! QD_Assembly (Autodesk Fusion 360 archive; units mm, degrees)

design "! QD_Assembly" references "Inlet Probe", "3/16  Stainless Steel Ball 9291K45", "PC085-1225-3380-SST-0880-CG-N-IN", "Sleeve", "Outlet Port", "Modeled Plateless Cylinder Housing", "PC085-1225-3380-SST-0880-CG-N-IN", "No. 19 1/16  PTFE O-ring 9559k114", "1.25  Bore, 1.5  Stroke Pneumatic Cylinder 4952K718", "Retainer", "3/4  Self Lock Snap Ring 98368A190"
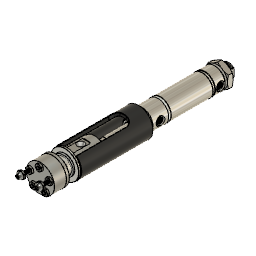
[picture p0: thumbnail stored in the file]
description: Part Number
part number: 92210A324_18-8 Stainless Steel Hex Drive Flat Head Screw
part number: 91841A195_Corrosion-Resistant 18-8 Stainless Steel Hex Nuts
part number: 92210A312_18-8 Stainless Steel Hex Drive Flat Head Screw
part number: 94301A125_Open-End Cap Nut
component_insert "Component Insert1"
component_insert "Component Insert2"
joint "Assemble" alignAngle 0 alignOffsetX 0 alignOffsetY 0 alignOffsetZ 0
component_insert "Component Insert3"
joint "Assemble" alignAngle 0 alignOffsetX 0 alignOffsetY 0 alignOffsetZ 0
joint "Assemble" alignAngle 0 alignOffsetX 0 alignOffsetY 0 alignOffsetZ 0
component_insert "Component Insert4"
joint "Assemble" alignAngle 0 alignOffsetX 0 alignOffsetY 0 alignOffsetZ 0
component_insert "Component Insert5"
joint "Assemble" alignAngle 0 alignOffsetX 0 alignOffsetY 0 alignOffsetZ 0
component_insert "Component Insert6"
step "GeometricRelationship1" Offset 0
joint "Assemble" alignAngle 0 alignOffsetX 0 alignOffsetY 0 alignOffsetZ 0
position "Position1"
component_insert "Component Insert8"
joint "Assemble" alignAngle 180 alignOffsetX 0 alignOffsetY 0 alignOffsetZ 0
component_insert "Component Insert9"
step "GeometricRelationship3" Offset 0
position "Position2"
joint "Assemble" alignAngle 0 alignOffsetX 0 alignOffsetY 0 alignOffsetZ 0
component_insert "Component Insert12"
joint "Assemble" alignAngle 0 alignOffsetX 0 alignOffsetY 0 alignOffsetZ 0
step "GeometricRelationship4" Offset 0
base_feature "Base Feature1"
step "GeometricRelationship5" Offset 0
base_feature "Base Feature1"
step "GeometricRelationship6" Offset 0
position "Position3"
circular_pattern "C-Pattern1" TotalAngle 360
circular_pattern "C-Pattern1" TotalAngle 360
component_insert "Component Insert13"
component_insert "Component Insert14"
base_feature "Base Feature1"
step "GeometricRelationship7" Offset 0
base_feature "Base Feature1"
step "GeometricRelationship8" Offset 10.16
position "Position4"
mirror "Mirror1" mirrorStitchTolerance 0.1001
mirror "Mirror1" mirrorStitchTolerance 0.1001
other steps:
create_component "CreateComponent1"
create_component "CreateComponent2"
create_component "CreateComponent3"
create_component "CreateComponent4"

design "PC085-1225-3380-SST-0880-CG-N-IN"
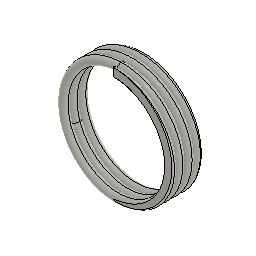
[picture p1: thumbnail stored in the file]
description: Part Number
part number: ANIMATE_PC
base_feature "Base Feature"

design "Retainer"
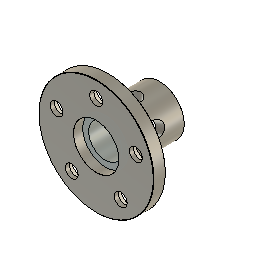
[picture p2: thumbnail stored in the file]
sketch "Sketch1" plane through (0, 0, 0) normal (1, 0, 0) x axis (0, 1, 0)
  line L1 (0, 8.7376) -> (0, 22.225)
  line L2 (3.556, 8.7376) -> (0, 8.7376)
  line L3 (3.556, 6.4389) -> (3.556, 8.7376)
  line L4 (24.638, 6.4389) -> (3.556, 6.4389)
  line L5 (24.638, 9.525) -> (24.638, 6.4389)
  line L6 (4.7625, 9.525) -> (24.638, 9.525)
  line L7 (4.7625, 22.225) -> (4.7625, 9.525)
  line L8 (0, 22.225) -> (4.7625, 22.225)
  line L9 (24.13, 9.144) -> (24.13, 9.525)
  line L10 (22.13, 9.144) -> (24.13, 9.144)
  line L11 (22.13, 9.525) -> (22.13, 9.144)
  point P1 (0, 0)
  point P3 (0, 8.7376)
  point P10 (24.13, 9.525)
  point P13 (22.13, 9.525)
  point P2 (0, 22.225)
  point P9 (4.7625, 22.225)
  point P4 (3.556, 8.7376)
  point P7 (24.638, 9.525)
  point P11 (24.13, 9.144)
  point P12 (22.13, 9.144)
  vertical L1
  perpendicular L1 L2
  perpendicular L2 L3
  perpendicular L3 L4
  perpendicular L4 L5
  perpendicular L5 L6
  perpendicular L6 L7
  perpendicular L1 L8
  vertical P1 P3
  coincident L6 P10
  perpendicular L6 L9
  perpendicular L5 L10
  coincident L6 P13
  perpendicular L6 L11
  dimension "d1" distance P2 P9 = 4.7625
  dimension "d2" distance P1 L4 = 6.4389 (= "( ( 0.5 + 0.006 + 0.001 ) / 2 ) * 1 in")
  dimension "d3" distance P1 L2 = 8.7376 (= "( ( 0.5 + 0.187 + 0.001 ) / 2 ) * 1 in")
  dimension "d4" distance P3 P4 = 3.556
  dimension "d5" distance P1 L8 = 22.225 (= "( 1.75 / 2 ) * 1 in")
  dimension "d6" distance P2 P7 = 24.638
  dimension "d7" distance P1 L6 = 9.525
  dimension "d45" distance P11 P12 = 2
  dimension "d46" distance P1 L10 = 9.144 (= "( 0.72 / 2 ) * 1 in")
  dimension "d47" distance L5 L9 = 0.508
revolve "Revolve1" sketch "Sketch1" AlongAngle 360
sketch "Sketch2" plane through (0, 0, 0) normal (1, 0, 0) x axis (0, 1, 0)
  line L1 (12.0759, 6.4389) -> (11.5318, 9.525)
  line L2 (4.7625, 9.525) -> (24.638, 9.525)
  line L3 (24.638, 6.4389) -> (3.556, 6.4389)
  line L4 (14.4189, 6.4389) -> (14.4189, 9.525)
  line L5 (12.2478, 5.4642) -> (11.5318, 9.525)
  line L6 (14.4189, 5.4642) -> (12.2478, 5.4642)
  line L7 (14.4189, 6.4389) -> (14.4189, 5.4642)
  line L8 (14.4189, 9.525) -> (17.306, 9.525)
  line L9 (16.59, 5.4642) -> (17.306, 9.525)
  line L10 (14.4189, 5.4642) -> (16.59, 5.4642)
  circle C1 centre (14.4189, 6.8644) radius 2.3813
  point P2 (11.5318, 9.525)
  point P3 (12.0759, 6.4389)
  point P8 (14.4189, 9.525)
  point P9 (14.4189, 6.4389)
  point P12 (17.306, 9.525)
  point P13 (14.4189, 9.525)
  point P10 (12.2478, 5.4642)
  point P14 (16.59, 5.4642)
  point P11 (14.4189, 5.4642)
  point P15 (14.4189, 5.4642)
  point P16 (14.4189, 6.8644)
  coincident P2 L2
  coincident P3 L3
  coincident L2 P8
  coincident L3 P9
  vertical L4
  parallel L1 L5
  perpendicular L4 L6
  perpendicular L3 L7
  symmetric P2 L4 P12
  symmetric P8 L4 P13
  symmetric L4 P10 P14
  symmetric L4 P11 P15
  coincident L4 P16
  tangent L5 C1
  dimension "d27" angle L1 L2 = 80
  dimension "d33" diameter C1 = 4.7625 (= "( 3 / 16 ) * 1 in")
  dimension "d44" distance P13 P16 = 2.6606 (= "( 0.1875 / 2 ) * 1 in + 0.011 in")
revolve "Revolve2" sketch "Sketch2" AlongAngle 360
circular_pattern "C-Pattern1" TotalAngle 360
sketch "Sketch4" plane through (0, 4.7625, 0) normal (0, 1, 0) x axis (-1, 0, 0)
  circle C1 centre (0, 16.129) radius 2.4892
  circle C2 centre (0, 0) radius 22.225
  circle C3 centre (0, 0) radius 9.525
  point P2 (0, 0)
  point P3 (0, 16.129)
  vertical P2 P3
  dimension "d18" diameter C1 = 4.9784
  dimension "d19" distance P2 P3 = 16.129
hole "Hole1" HoleDepth 5.08 HoleDiameter 4.9784 TipAngle 118 CSDiameter 10.4394 CSAngle 82
circular_pattern "C-Pattern2" TotalAngle 360
fillet "Fillet2" radius 0.127
fillet "Fillet3" radius 0.254
chamfer "Chamfer4" distance 0.127
chamfer "Chamfer5" distance 0.0254
fillet "Fillet4" radius 1.016
sketch "Sketch5" plane through (0, 3.556, 0) normal (0, -1, 0) x axis (1, 0, 0)
  circle C1 centre (0, 0) radius 6.4389
  circle C2 centre (0, 0) radius 8.7376

design "Outlet Port"
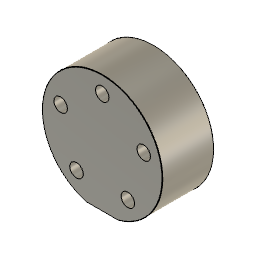
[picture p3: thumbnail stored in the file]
sketch "Sketch1" plane through (0, 0, 0) normal (1, 0, 0) x axis (0, 1, 0)
  line L1 (109.277, 0) -> (0, 0)
  line L2 (0, 6.604) -> (0, 22.225)
  line L3 (19.05, 6.604) -> (0, 6.604)
  line L4 (0, 22.225) -> (19.05, 22.225)
  line L5 (19.05, 11.9507) -> (19.05, 22.225)
  line L6 (17.6784, 11.9507) -> (19.05, 11.9507)
  line L7 (17.6784, 9.3345) -> (17.6784, 11.9507)
  line L8 (19.05, 9.3345) -> (17.6784, 9.3345)
  line L9 (19.05, 6.604) -> (19.05, 9.3345)
  line L10 (0, 0) -> (0, 6.604)
  line L11 (19.05, 0) -> (19.05, 6.604)
  line L12 (19.05, 0) -> (0, 0)
  point P1 (0, 0)
  point P2 (0, 0)
  point P5 (0, 6.604)
  point P8 (19.05, 11.9507)
  point P11 (19.05, 9.3345)
  point P12 (0, 0)
  point P13 (19.05, 0)
  point P14 (0, 0)
  point P4 (0, 22.225)
  point P7 (19.05, 22.225)
  point P9 (17.6784, 11.9507)
  coincident P1 P2
  horizontal L1
  vertical L2
  perpendicular L2 L3
  perpendicular L2 L4
  perpendicular L4 L5
  perpendicular L5 L6
  perpendicular L6 L7
  perpendicular L7 L8
  perpendicular L3 L9
  vertical P1 P5
  vertical P8 P11
  coincident P1 P12
  coincident L1 P13
  perpendicular L1 L11
  coincident P1 P14
  dimension "d1" distance P4 P7 = 19.05
  dimension "d2" distance P1 L4 = 22.225 (= "( 1.75 / 2 ) * 1 in")
  dimension "d3" distance P1 L3 = 6.604 (= "0.25 in + 0.01 in")
  dimension "d4" distance L1 L6 = 11.9507
  dimension "d5" distance L1 L8 = 9.3345
  dimension "d6" distance P8 P9 = 1.3716
revolve "Revolve1" sketch "Sketch1" AlongAngle 360
sketch "Sketch2" plane through (0, 0, 0) normal (0, -1, 0) x axis (1, 0, 0)
  circle C1 centre (0, 16.129) radius 2.4892
  circle C2 centre (0, 0) radius 22.225
  point P1 (0, 0)
  point P2 (0, 16.129)
  vertical P1 P2
  dimension "d10" diameter C1 = 4.9784
  dimension "d24" distance P1 P2 = 16.129
extrude "Extrude1" cut sketch "Sketch2" profile of C1 to an object
circular_pattern "C-Pattern1" TotalAngle 360
work_plane "WorkPlane1" RotateAngle 90
sketch "Sketch3" plane through (0, 0, 0) normal (0, -1, 0) x axis (1, 0, 0)
  circle C1 centre (-15.3396, 4.9841) radius 2.4892
  circle C2 centre (-9.4804, -13.0486) radius 2.4892
  circle C3 centre (9.4804, -13.0486) radius 2.4892
  circle C4 centre (15.3396, 4.9841) radius 2.4892
  circle C5 centre (0, 16.129) radius 2.4892
  circle C6 centre (0, 0) radius 22.225
hole "Hole2" HoleDepth 15.621 HoleDiameter 13.716 TipAngle 180
chamfer "Chamfer3" distance 0.127
chamfer "Chamfer4" distance 0.127
sketch "Sketch7" plane through (0, 0, -22.225) normal (0, 0, -1) x axis (-1, 0, 0)
  line L1 (6.985, 15.875) -> (-6.985, 15.875)
  line L2 (6.985, 1.905) -> (6.985, 15.875)
  line L3 (-6.985, 1.905) -> (6.985, 1.905)
  line L4 (-6.985, 15.875) -> (-6.985, 1.905)
  line L5 (0, 4.9156) -> (0, 1.905)
  line L6 (-1.263, 8.89) -> (6.985, 8.89)
  line L7 (0, 19.05) -> (0, 0)
  point P6 (0, 1.905)
  point P8 (6.985, 8.89)
  point P1 (0, 0)
  point P10 (0, 0)
  point P7 (0, 4.9156)
  point P2 (-6.985, 15.875)
  point P3 (6.985, 15.875)
  horizontal L1
  vertical L2
  horizontal L3
  vertical L4
  equal L1 L2
  midpoint L3 P6
  perpendicular L3 L5
  midpoint L2 P8
  perpendicular L2 L6
  coincident P1 P10
  vertical L7
  coincident P7 L7
  dimension "d33" distance P2 P3 = 13.97
  dimension "d34" distance P1 L6 = 8.89
extrude "Extrude2" add sketch "Sketch7" profile of L1 L2 L3 L4 against normal blind 2.54
sketch "Sketch8" plane through (0, 0, -22.225) normal (0, 0, -1) x axis (1, 0, 0)
  line L1 (6.985, -15.875) -> (0, -15.875)
  line L2 (6.985, -1.905) -> (6.985, -15.875)
  line L3 (0, -1.905) -> (6.985, -1.905)
  line L4 (-6.985, -1.905) -> (0, -1.905)
  line L5 (-6.985, -15.875) -> (-6.985, -1.905)
  line L6 (0, -15.875) -> (-6.985, -15.875)
  line L7 (0, -19.05) -> (0, 0)
  line L8 (-22.098, -19.05) -> (22.098, -19.05)
  line L9 (22.098, 0) -> (-22.098, 0)
  line L10 (22.098, 0) -> (-22.098, 0)
  line L11 (22.098, -19.05) -> (22.098, 0)
  line L12 (-22.098, -19.05) -> (22.098, -19.05)
  line L13 (-22.098, 0) -> (-22.098, -19.05)
  circle C1 centre (0, -8.89) radius 1.27
  point P1 (0, 0)
  point P9 (0, 0)
  point P10 (0, -19.05)
  point P8 (0, -8.89)
  point P11 (22.098, -19.05)
  point P17 (22.098, -19.05)
  point P13 (-22.098, 0)
  point P15 (-22.098, 0)
  coincident P1 P9
  perpendicular L6 L7
  coincident P10 L8
  coincident P8 L7
  horizontal L10
  vertical L11
  horizontal L12
  vertical L13
  coincident P11 P17
  coincident P13 P15
  dimension "d37" diameter C1 = 2.54
  dimension "d43" distance P8 L9 = 8.89
hole "Hole3" HoleDepth 20.32 HoleDiameter 10.7188 TipAngle 118
extrude "Extrude3" cut sketch "Sketch8" profile of L1 L2 L3 L4 L5 L6 C1 L10 L11 L12 L13 against normal blind 0.889
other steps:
thread "Thread2" ThreadOffset 0 ThreadDepth 0

design "1.25  Bore, 1.5  Stroke Pneumatic Cylinder 4952K718"
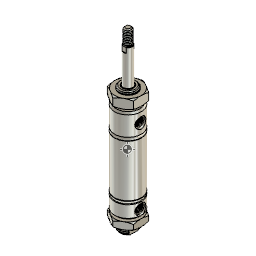
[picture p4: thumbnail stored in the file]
description: Part Number
part number: 4952K718_Round Body Air Cylinder
base_feature "Base Feature"
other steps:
create_component "CreateComponent1"

design "3/16  Stainless Steel Ball 9291K45"
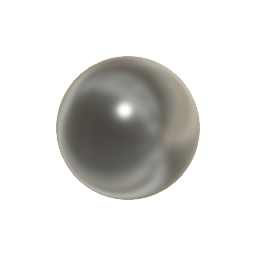
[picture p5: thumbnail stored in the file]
description: Part Number
part number: 9291K45_Tight-Tolerance Multipurpose 304 Stainless Steel Ball
base_feature "Base Feature"
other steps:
create_component "CreateComponent1"

design "No. 19 1/16  PTFE O-ring 9559k114"
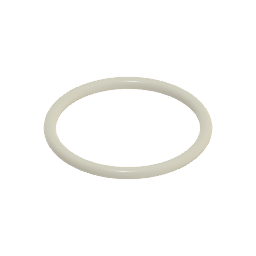
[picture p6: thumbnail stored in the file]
description: Part Number
part number: 9559K114_Ultra-Chemical-Resistant Rigid PTFE O-Ring
base_feature "Base Feature"
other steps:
create_component "CreateComponent1"

design "Modeled Plateless Cylinder Housing"
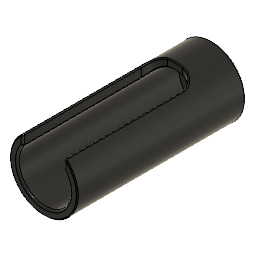
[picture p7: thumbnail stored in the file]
parameter "d85" = 360
parameter "d95" = 360
sketch "Sketch1" plane through (0, 0, 0) normal (1, 0, 0) x axis (0, 1, 0)
  line L1 (104.14, 17.78) -> (0, 17.78)
  line L2 (0, 17.78) -> (0, 22.86)
  line L3 (114.3, 22.86) -> (0, 22.86)
  line L4 (0, 0) -> (114.3, 0)
  line L5 (114.3, 17.78) -> (104.14, 17.78)
  line L6 (114.3, 22.86) -> (114.3, 17.78)
  line L7 (114.3, 8.7313) -> (114.3, 17.78)
  line L8 (109.22, 8.7313) -> (114.3, 8.7313)
  line L9 (109.22, 17.78) -> (109.22, 8.7313)
  point P5 (114.3, 0)
  point P6 (114.3, 22.86)
  point P3 (0, 17.78)
  point P4 (104.14, 17.78)
  point P2 (0, 22.86)
  point P1 (0, 0)
  point P7 (0, 0)
  point P11 (109.22, 17.78)
  point P9 (114.3, 8.7313)
  point P10 (109.22, 8.7313)
  vertical P5 P6
  horizontal P3 P4
  vertical P2 P3
  vertical P1 P3
  horizontal P2 P6
  coincident P1 P7
  parallel L1 L5
  perpendicular L3 L6
  perpendicular L5 L7
  perpendicular L6 L8
  coincident L5 P11
  perpendicular L5 L9
  dimension "d1" distance P2 P6 = 114.3
  dimension "d3" distance P1 L1 = 17.78
  dimension "d14" distance L1 L3 = 5.08
  dimension "d110" = 17.4625
  dimension "d113" distance P9 P10 = 5.08
  dimension "d82" Offset = 0
  dimension "d83" Angle = 0
  dimension "d91" Offset = 0
  dimension "d92" Offset = 0
  dimension "d93" Offset = 0
  dimension "d98" AlongDistance = -6.35
  dimension "d99" TaperAngle = 0
  dimension "d101" Radius = 15.24
  dimension "d103" Radius = 0.635
  dimension "d105" Radius = 0.635
revolve "Revolve1" sketch "Sketch1" AlongAngle 360
sketch "Sketch3" plane through (0, 0, 0) normal (0, 0, 1) x axis (1, 0, 0)
  line L1 (13.97, 0) -> (-13.97, 0)
  line L2 (13.97, 88.9) -> (13.97, 0)
  line L3 (-13.97, 88.9) -> (13.97, 88.9)
  line L4 (-13.97, 0) -> (-13.97, 88.9)
  point P1 (0, 0)
  point P2 (-13.97, 0)
  point P3 (13.97, 0)
  point P5 (-13.97, 88.9)
  horizontal L1
  vertical L2
  horizontal L3
  vertical L4
  coincident P1 L1
  midpoint P1 L1
  dimension "d7" distance P2 P3 = 27.94
  dimension "d8" distance P2 P5 = 88.9
extrude "Extrude1" cut sketch "Sketch3" along normal blind 30.48
chamfer "Chamfer2" distance 0.508
fillet "Fillet1" radius 8.89
sketch "Sketch4" plane through (0, 114.3, 0) normal (0, 1, 0) x axis (-1, 0, 0)
  line L1 (5.5825, -29.1664) -> (2.8706, -33.9505)
  line L2 (2.7953, -24.4258) -> (5.5825, -29.1664)
  line L3 (-2.7038, -24.4693) -> (2.7953, -24.4258)
  line L4 (-5.4157, -29.2534) -> (-2.7038, -24.4693)
  line L5 (-2.6284, -33.994) -> (-5.4157, -29.2534)
  line L6 (2.8706, -33.9505) -> (-2.6284, -33.994)
  line L7 (28.042, 9.9366) -> (22.5429, 9.8931)
  line L8 (30.7539, 14.7207) -> (28.042, 9.9366)
  line L9 (27.9667, 19.4613) -> (30.7539, 14.7207)
  line L10 (22.4676, 19.4178) -> (27.9667, 19.4613)
  line L11 (19.7557, 14.6337) -> (22.4676, 19.4178)
  line L12 (22.5429, 9.8931) -> (19.7557, 14.6337)
  line L13 (-22.6263, 19.3168) -> (-19.8391, 14.5762)
  line L14 (-28.1254, 19.2733) -> (-22.6263, 19.3168)
  line L15 (-30.8373, 14.4892) -> (-28.1254, 19.2733)
  line L16 (-28.0501, 9.7486) -> (-30.8373, 14.4892)
  line L17 (-22.551, 9.7921) -> (-28.0501, 9.7486)
  line L18 (-19.8391, 14.5762) -> (-22.551, 9.7921)
  line L19 (-5.4715, -22.1955) -> (-5.4157, -29.2534)
  line L20 (5.5272, -22.1817) -> (5.5825, -29.1664)
  line L21 (21.9577, 6.3593) -> (28.042, 9.9366)
  line L22 (16.4463, 15.8776) -> (22.4676, 19.4178)
  line L23 (-16.4862, 15.8362) -> (-22.6263, 19.3168)
  line L24 (-21.9736, 6.3041) -> (-28.0501, 9.7486)
  circle C1 centre (0, 0) radius 22.86
  circle C2 centre (0, 0) radius 12.7
  circle C3 centre (0.0834, -29.2099) radius 2.4765
  circle C4 centre (25.2548, 14.6772) radius 2.4765
  circle C5 centre (-25.3382, 14.5327) radius 2.4765
  circle C6 centre (0.0834, -29.2099) radius 5.4993
  circle C7 centre (25.2548, 14.6772) radius 5.4993
  circle C8 centre (-25.3382, 14.5327) radius 5.4993
  arc A1 centre (0, 0) radius 22.86 clockwise from (0, 0) to (0, 0)
  circle C9 centre (0, 0) radius 22.86
  circle C10 centre (0, 0) radius 8.7313
  point P1 (0, 0)
  point P3 (0, 0)
  point P4 (0.0834, -29.2099)
  point P13 (0.0834, -29.2099)
  point P7 (2.8706, -33.9505)
  point P30 (0, 0)
  point P31 (-5.4715, -22.1955)
  point P32 (5.5272, -22.1817)
  coincident P1 P3
  coincident P4 P13
  concentric C3 C6
  coincident P7 C6
  coincident P3 P30
  coincident C1 P31
  tangent C6 L19
  coincident A1 P32
  tangent C6 L20
  parallel L19 L20
  dimension "d17" diameter C3 = 4.953
  dimension "d18" distance P3 P4 = 29.21
  dimension "d24" distance L3 L6 = 9.525
  dimension "d20" C-Pattern1-Angle = 360
  dimension "d26" C-Pattern2-Angle = 360
  dimension "d97" C-Pattern3-Angle = 360
fillet "Fillet20" radius 1.27
fillet "Fillet23" radius 0.635 0.635
fillet "Fillet24" radius 1.27

design "Sleeve"
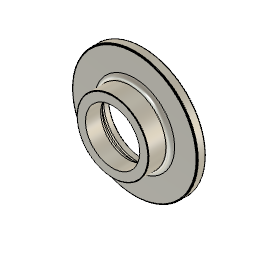
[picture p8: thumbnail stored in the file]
sketch "Sketch1" plane through (0, 0, 0) normal (1, 0, 0) x axis (0, 1, 0)
  line L1 (0, 9.6012) -> (0, 12.7)
  line L2 (5.9182, 9.6012) -> (0, 9.6012)
  line L3 (8.382, 12.065) -> (5.9182, 9.6012)
  line L4 (10.922, 12.065) -> (8.382, 12.065)
  line L5 (10.922, 22.225) -> (10.922, 12.065)
  line L6 (7.747, 22.225) -> (10.922, 22.225)
  line L7 (7.747, 12.7) -> (7.747, 22.225)
  line L8 (0, 12.7) -> (7.747, 12.7)
  line L9 (25.8911, 9.6012) -> (5.9182, 9.6012)
  point P1 (0, 0)
  point P2 (0, 9.6012)
  point P4 (8.382, 12.065)
  point P5 (10.922, 12.065)
  point P6 (10.922, 22.225)
  point P7 (7.747, 22.225)
  point P8 (7.747, 12.7)
  point P9 (0, 12.7)
  vertical L1
  perpendicular L1 L2
  perpendicular L1 L4
  perpendicular L4 L5
  perpendicular L5 L6
  perpendicular L6 L7
  perpendicular L1 L8
  vertical P1 P2
  parallel L2 L9
  dimension "d1" distance P1 L2 = 9.6012 (= "0.375 in + 0.003 in")
  dimension "d2" distance P1 L8 = 12.7
  dimension "d4" angle L3 L9 = 45
  dimension "d5" distance P4 P5 = 2.54
  dimension "d6" distance P6 P7 = 3.175
  dimension "d7" distance P1 L6 = 22.225
  dimension "d8" distance P8 P9 = 7.747
  dimension "d9" distance P1 L4 = 12.065
revolve "Revolve1" sketch "Sketch1" AlongAngle 360
fillet "Fillet1" radius 1.27
fillet "Fillet2" radius 1.524
chamfer "Chamfer2" distance 0.127
chamfer "Chamfer3" distance 0.254
chamfer "Chamfer4" distance 0.127
fillet "Fillet3" radius 0.254
fillet "Fillet4" radius 0.127
fillet "Fillet5" radius 1.27

design "Inlet Probe"
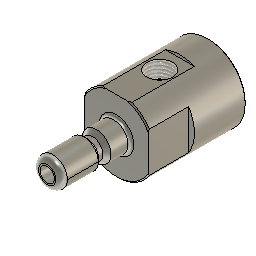
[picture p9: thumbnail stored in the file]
sketch "Sketch1" plane through (0, 0, 0) normal (1, 0, 0) x axis (0, 1, 0)
  line L1 (0, 0) -> (0, 6.35)
  line L2 (71.12, 16.51) -> (71.12, 0)
  line L3 (30.48, 6.35) -> (30.48, 16.51)
  line L4 (16.129, 6.35) -> (0, 6.35)
  line L5 (17.907, 4.572) -> (16.129, 6.35)
  line L6 (19.939, 4.572) -> (17.907, 4.572)
  line L7 (21.717, 6.35) -> (19.939, 4.572)
  line L8 (30.48, 6.35) -> (21.717, 6.35)
  line L9 (9.906, 4.572) -> (17.907, 4.572)
  line L10 (71.12, 0) -> (0, 0)
  line L11 (71.12, 16.51) -> (30.48, 16.51)
  line L12 (9.271, 6.35) -> (9.271, 14.9337)
  line L13 (21.717, 6.35) -> (16.129, 6.35)
  point P1 (0, 0)
  point P2 (0, 0)
  point P3 (71.12, 0)
  point P4 (71.12, 16.51)
  point P5 (30.48, 16.51)
  point P14 (9.271, 6.35)
  point P6 (30.48, 6.35)
  point P9 (17.907, 4.572)
  point P10 (19.939, 4.572)
  point P8 (16.129, 6.35)
  point P7 (0, 6.35)
  vertical L1
  vertical P1 P2
  perpendicular L1 L4
  perpendicular L1 L6
  perpendicular L5 L7
  perpendicular L3 L8
  parallel L6 L9
  equal L5 L7
  vertical L2
  horizontal P2 P3
  coincident P1 P2
  horizontal P4 P5
  coincident L4 P14
  perpendicular L4 L12
  vertical P5 P6
  dimension "d1" angle L5 L9 = 45
  dimension "d2" distance P9 P10 = 2.032
  dimension "d4" distance L4 L10 = 6.35
  dimension "d6" distance L10 L11 = 16.51
  dimension "d7" distance P1 L6 = 4.572
  dimension "d8" distance P1 L12 = 9.271
  dimension "d9" distance P8 L12 = 6.858
  dimension "d11" distance P1 P3 = 71.12
  dimension "d15" distance P6 P7 = 30.48
revolve "Revolve1" sketch "Sketch1" AlongAngle 360
fillet "Fillet1" radius 1.27
fillet "Fillet2" radius 2.54
chamfer "Chamfer1" distance 0.508
work_plane "WorkPlane1" RotateAngle 0
hole "Hole2" HoleDepth 10.16 (= "1 in - 0.6 in") HoleDiameter 7.9756 TipAngle 118
hole "Hole3" HoleDepth 49.53 HoleDiameter 6.35 TipAngle 118
sketch "Sketch5" plane through (0, 0, 0) normal (0, 1, 0) x axis (1, 0, 0)
work_plane "WorkPlane2" AlongDistance 17.145
sketch "Sketch7" plane through (0, 17.145, 0) normal (0, 1, 0) x axis (1, 0, 0)
  line L1 (0, -5.334) -> (0, 0)
  circle C1 centre (0, -5.334) radius 0.0635
  circle C2 centre (5.0729, -1.6483) radius 0.0635
  circle C3 centre (3.1352, 4.3153) radius 0.0635
  circle C4 centre (-3.1352, 4.3153) radius 0.0635
  circle C5 centre (-5.0729, -1.6483) radius 0.0635
  point P1 (0, 0)
  point P2 (0, -5.334)
  point P3 (0, 0)
  point P4 (0, -5.334)
  vertical P1 P2
  coincident P1 P3
  vertical L1
  coincident P2 P4
  dimension "d66" diameter C1 = 0.127
  dimension "d68" C-Pattern1-Angle = 360
split_face "SplitFace3"
split_face "SplitFace4"
split_face "SplitFace5"
split_face "SplitFace6"
split_face "SplitFace7"
sketch "Sketch8" plane through (0, 30.48, 0) normal (0, -1, 0) x axis (1, 0, 0)
  line L1 (-19.05, 12.7) -> (-13.97, 12.7)
  line L2 (-19.05, -12.7) -> (-19.05, 12.7)
  line L3 (-13.97, -12.7) -> (-19.05, -12.7)
  line L4 (-13.97, 12.7) -> (-13.97, -12.7)
  line L5 (19.05, 12.7) -> (13.97, 12.7)
  line L6 (19.05, -12.7) -> (19.05, 12.7)
  line L7 (13.97, -12.7) -> (19.05, -12.7)
  line L8 (13.97, 12.7) -> (13.97, -12.7)
  line L9 (6.35, 15.24) -> (-6.35, 15.24)
  line L10 (6.35, 17.78) -> (6.35, 15.24)
  line L11 (-6.35, 17.78) -> (6.35, 17.78)
  line L12 (-6.35, 15.24) -> (-6.35, 17.78)
  circle C1 centre (0, 0) radius 7.62
  circle C2 centre (0, 0) radius 16.002
  point P11 (0, 0)
  horizontal L1
  vertical L2
  horizontal L3
  vertical L4
  horizontal L5
  vertical L6
  horizontal L7
  vertical L8
  horizontal L9
  vertical L10
  horizontal L11
  vertical L12
  dimension "d71" distance L4 P11 = 13.97
  dimension "d72" distance L8 P11 = 13.97
extrude "Extrude3" cut sketch "Sketch8" profile of C2 L1 L2 L3 L4 L5 L6 L7 L8 against normal blind 17.78
sketch "Sketch9" plane through (0, 0, 16.51) normal (0, 0, 1) x axis (1, 0, 0)
  line L1 (-13.97, 30.48) -> (13.97, 30.48)
  line L2 (7.62, 58.3691) -> (-7.62, 58.3691)
  line L3 (7.62, 27.94) -> (7.62, 58.3691)
  line L4 (-7.62, 27.94) -> (7.62, 27.94)
  line L5 (-7.62, 58.3691) -> (-7.62, 27.94)
  circle C1 centre (0, 49.53) radius 13.97
  point P2 (0, 49.53)
  horizontal L2
  vertical L3
  horizontal L4
  vertical L5
  dimension "d73" diameter C1 = 27.94
  dimension "d82" distance P2 L1 = 19.05
hole "Hole1" HoleDepth 20.32 HoleDiameter 10.7188 TipAngle 118
split_face "SplitFace8"
extrude "Extrude5" cut sketch "Sketch8" profile of C2 L9 L10 L11 L12 against normal blind 27.94
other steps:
thread "Thread2" ThreadOffset 0 ThreadDepth 8.6081
thread "Thread1" ThreadOffset 0 ThreadDepth 0

design "3/4  Self Lock Snap Ring 98368A190"
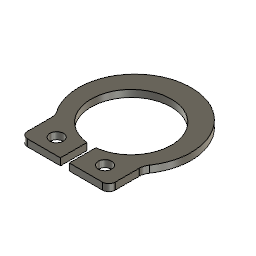
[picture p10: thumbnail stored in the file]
description: Part Number
part number: 98368A190_Self-Locking External Retaining Rings
base_feature "Base Feature"
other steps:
create_component "CreateComponent1"

design "PC085-1225-3380-SST-0880-CG-N-IN"
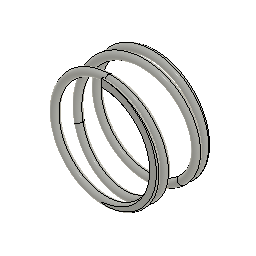
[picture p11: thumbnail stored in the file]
description: Part Number
part number: ANIMATE_PC
base_feature "Base Feature"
